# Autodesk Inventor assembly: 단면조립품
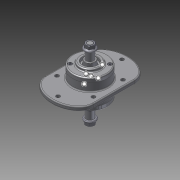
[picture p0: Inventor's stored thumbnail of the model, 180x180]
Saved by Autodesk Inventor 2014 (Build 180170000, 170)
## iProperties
Created: 2015-02
Part Number: 단면조립품
Document SubType Name: Assembly
Designer: basic
Author: basic
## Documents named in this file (10)
- C:\Users\basic\Desktop\450207V1002\단면조립품.iam
- C:\Users\basic\Desktop\450207V1002\부품1.ipt
- C:\Users\basic\Desktop\450207V1002\3-축.ipt
- C:\Users\basic\Desktop\450207V1002\9-M16-너트.ipt
- C:\Users\basic\Desktop\450207V1002\4-V벨트풀리.ipt
- C:\Users\basic\Desktop\450207V1002\5-체인 스프로킷.ipt
- C:\Users\basic\Desktop\450207V1002\6-베어링 6206.ipt
- C:\Users\basic\Desktop\450207V1002\11-키 6x6.ipt
- C:\Users\basic\Desktop\450207V1002\2-커버.ipt
- C:\Users\basic\Desktop\450207V1002\10-M6.ipt
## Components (19 placed, 8 different names)
1. 3-축:1
2. 9-M16 너트:1
3. 9-M16 너트:2
4. 4-V벨트풀리:1
5. 5-체인 스프로킷:1
6. 6-베어링 6206:1
7. 6-베어링 6206:2
8. 11-키 6x6:1
9. 11-키 6x6:2
10. 2-커버:1
11. 2-커버:2
12. 10-M6:1
13. 10-M6:2
14. 10-M6:3
15. 10-M6:4
16. 10-M6:5
17. 10-M6:6
18. 10-M6:7
19. 10-M6:8
